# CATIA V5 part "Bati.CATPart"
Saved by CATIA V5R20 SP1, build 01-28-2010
Part number: Bati
Bounding box of the stored display mesh (mm): x -60 to 60, y -20 to 20, z 0 to 82.921
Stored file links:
  E:\EDELI\gcausse\Edeli_2012_233_gcausse\Bati.CATPart
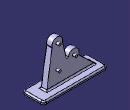
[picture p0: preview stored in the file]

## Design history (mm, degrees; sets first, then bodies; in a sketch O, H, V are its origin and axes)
Body1 (main body)
  Sketch1 on xy-plane, origin (0, 0, 0), H (1, 0, 0), V (0, 1, 0)
    line L1 (-60, 20) -> (60, 20)
    line L2 (60, 20) -> (60, -20)
    line L3 (60, -20) -> (-60, -20)
    line L4 (-60, -20) -> (-60, 20)
    horizontal: L1 H, L3 H
    vertical: L2 V, L4 V
  Pad1: profile Sketch1, direction (0, 0, 1), length 5
  Fillet1: radius 5, on edge [face of Pad1 from Sketch1.L1 | face of Pad1 from Sketch1.L2]; edge [face of Pad1 from Sketch1.L4 | face of Pad1 from Sketch1.L1]; edge [face of Pad1 from Sketch1.L3 | face of Pad1 from Sketch1.L4]; edge [face of Pad1 from Sketch1.L2 | face of Pad1 from Sketch1.L3]
  Sketch2 on end face of Pad1, origin (0, 0, 5), H (1, 0, 0), V (0, 1, 0)
    line L1 (-60, 5) -> (60, 5)
    line L2 (60, 5) -> (60, -5)
    line L3 (60, -5) -> (-60, -5)
    line L4 (-60, -5) -> (-60, 5)
    reference projected line E1 (-60, -20) -> (60, -20) from edge [face of Pad1 from Sketch1.L3 | end face of Pad1]
    reference projected line E2 (60, 20) -> (-60, 20) from edge [face of Pad1 from Sketch1.L1 | end face of Pad1]
    distance L1 E1 = 25
    distance L3 E2 = 25
    horizontal: L1 H, L3 H
    vertical: L2 V, L4 V
  Pad2: profile Sketch2, direction (0, 0, 1), length 80
  Sketch3 on face of Pad2 from Sketch2.L1, origin (0, 5, 0), H (-1, 0, 0), V (0, 0, 1)
  Sketch4 on face of Pad2 from Sketch2.L1, origin (0, 5, 0), H (-1, 0, 0), V (0, 0, 1)
    line L1 (-39.1902, 5) -> (-29.1902, 70.2141)
    line L2 (-10, 70) -> (0, 30)
    point P3 (0, 30)
    line L3 (0, 30) -> (2.2361, 34.4721)
    line L4 (20.1246, 34.4721) -> (50.8098, 5)
    arc A1 centre (-19.5637, 72.9216) radius 10 from (-29.1902, 70.2141) to (-10, 70) cw
    point P9 (-12.5, 80)
    arc A2 centre (11.1803, 38.9443) radius 10 from (2.2361, 34.4721) to (20.1246, 34.4721) cw
    line L5 (50.8098, 5) -> (70.8098, 5)
    line L6 (70.8098, 5) -> (70.8098, 85)
    line L7 (70.8098, 85) -> (-69.1902, 85)
    line L8 (-69.1902, 85) -> (-69.1902, 5)
    point P14 (-69.1902, 5)
    line L9 (-69.1902, 5) -> (-39.1902, 5)
    reference projected line E1 (-60, 5) -> (60, 5) from edge [end face of Pad1 | face of Pad2 from Sketch2.L1]
    radius A2 = 10
    radius A1 = 10
    length L3 = 5
    coincidence: P3 V, A1 P9, P9 L2, P14 L5, L9 E1
    horizontal: L5 H, L7 H, L9 H
    vertical: L6 V, L8 V
  Pocket1: profile Sketch4, direction (0, -1, 0), length 10
  Fillet2: radius 2.5, on edge [face of Pocket1 | face of Pad2 from Sketch2.L1]; edge [face of Pocket1 from Sketch4.L1 | face of Pocket1]; edge [face of Pocket1 | face of Pad2 from Sketch2.L3]; face of Pocket1
  Fillet3: radius 2, on edge [face of Pocket1 from Sketch4.L4 | face of Pocket1 from Sketch4.A2]; edge [face of Pocket1 from Sketch4.A2 | face of Pocket1 from Sketch4.L3]
  Fillet4: radius 2, on edge [face of Pocket1 from Sketch4.L2 | face of Pocket1 from Sketch4.A1]; edge [face of Pocket1 from Sketch4.A1 | face of Pocket1 from Sketch4.L1]
  Sketch5 on face of Pad2 from Sketch2.L1, origin (0, 5, 0), H (-1, 0, 0), V (0, 0, 1)
    circle A1 centre (-19.5637, 72.9216) radius 2.5
    point P1 (-19.5637, 72.9216)
    reference projected arc E1 centre (-19.5637, 72.9216) radius 10 from (-10, 70) to (-29.1902, 70.2141) ccw from edge [face of Pad2 from Sketch2.L1 | face of Pocket1 from Sketch4.A1]
    reference projected arc E2 centre (-19.5637, 72.9216) radius 10 from (-10, 70) to (-29.1902, 70.2141) ccw from edge [face of Pad2 from Sketch2.L1 | face of Pocket1 from Sketch4.A1]
    circle A2 centre (11.1803, 38.9443) radius 2.5
    reference projected arc E3 centre (11.1803, 38.9443) radius 10 from (20.1246, 34.4721) to (2.2361, 34.4721) ccw from edge [face of Pad2 from Sketch2.L1 | face of Pocket1 from Sketch4.A2]
    reference projected arc E4 centre (11.1803, 38.9443) radius 10 from (20.1246, 34.4721) to (2.2361, 34.4721) ccw from edge [face of Pad2 from Sketch2.L1 | face of Pocket1 from Sketch4.A2]
    circle A3 centre (-19.5637, 29.9216) radius 2.5
    point P3 (-19.5637, 29.9216)
    radius E2 = 10 (reference)
    radius A1 = 2.5
    radius A2 = 2.5
    radius E4 = 10 (reference)
    radius A3 = 2.5
    distance P1 P3 = 43
    concentricity: E1 A1, A2 E3
  Pad3: profile Sketch5, direction (0, 1, 0), length 5
  Fillet5: radius 2, on edge [face of Pocket1 from Sketch4.L3 | face of Pocket1 from Sketch4.L2]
